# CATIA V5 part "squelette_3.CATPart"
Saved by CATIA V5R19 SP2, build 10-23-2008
Part number: squelette_3
Publications: "Point.1", "Point.2", "Point.3", "Droite.1", "Droite.2", "Droite.3"
Bounding box of the stored display mesh (mm): x -10 to 10, y -34 to 74, z -3 to 3
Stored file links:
  M:\EU_thinkMotion\IAO_2010\iao\IAO_MMS_Groupe2\IAO_MMS_Groupe2\sdubois\sdubois\sdubois\IAO_mecanisme\squelette_3.CATPart
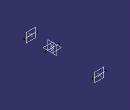
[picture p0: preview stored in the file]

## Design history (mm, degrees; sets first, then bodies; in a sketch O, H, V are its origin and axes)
Set1
  Point1: (0, 74, 0)
  Point2: (0, 0, 0)
  Point3: (0, -34, 0)
  Line1: type PtDir, RefPoint Point3, Direction yz-plane, Start -10, End 10
  Line2: type PtDir, RefPoint Point2, Direction yz-plane, Start -10, End 10
  Line3: type PtDir, RefPoint Point1, Direction yz-plane, Start -10, End 10
  Plane1: type OffsetPt, RefPlane zx-plane, RefPoint Point1
  Plane2: type OffsetPt, RefPlane zx-plane, RefPoint Point3
  Point4: (0, 0, 3)
  Point5: (0, 0, -3)
Body1 (main body)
